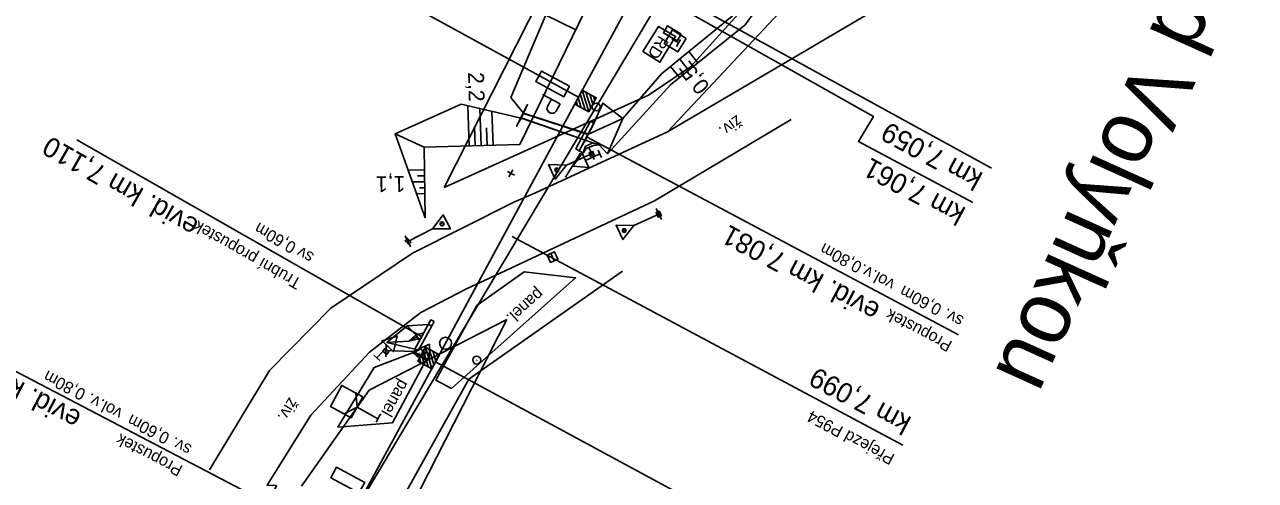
# Model space of a CAD drawing. Extents: x -795094 to -794639, y -1135368 to -1134681.
# Drawn here: x -794952.7 to -794797.7, y -1135065.2 to -1135007.8 of the extents above; entities that cross this region are included whole.
import ezdxf

# ---------------------------------------------------------------- set-up
doc = ezdxf.new("R2010")
doc.units = 0
for name, color, linetype in [('0381KM005-009P - Vrstva 1', 7, 'Continuous'), ('0381KM005-009P - Vrstva 12', 7, 'Continuous'), ('0381KM005-009P - Vrstva 13', 7, 'Continuous'), ('0381KM005-009P - Vrstva 16', 7, 'Continuous'), ('0381KM005-009P - Vrstva 17', 7, 'Continuous'), ('0381KM005-009P - Vrstva 19', 7, 'Continuous'), ('0381KM005-009P - Vrstva 2', 7, 'Continuous'), ('0381KM005-009P - Vrstva 23', 7, 'Continuous'), ('0381KM005-009P - Vrstva 25', 7, 'Continuous'), ('0381KM005-009P - Vrstva 28', 7, 'Continuous'), ('0381KM005-009P - Vrstva 3', 7, 'Continuous'), ('0381KM005-009P - Vrstva 33', 7, 'Continuous'), ('0381KM005-009P - Vrstva 4', 7, 'Continuous'), ('0381KM005-009P - Vrstva 43', 7, 'Continuous'), ('0381KM005-009P - Vrstva 48', 7, 'Continuous'), ('0381KM005-009P - Vrstva 49', 7, 'Continuous'), ('0381KM005-009P - Vrstva 51', 7, 'Continuous'), ('0381KM005-009P - Vrstva 7', 7, 'Continuous'), ('hran DP - hran DP', 7, 'Continuous'), ('vyt_sit - polygon', 7, 'Continuous')]:
    doc.layers.add(name, color=color, linetype=linetype)

msp = doc.modelspace()

# ---------------------------------------------------------------- linework, layer by layer
at = {"layer": '0381KM005-009P - Vrstva 1'}
for points in [[(-794874.77, -1135001.82), (-794875.27, -1135002.76), (-794882.94, -1135016.95), (-794888.88, -1135027.93)], [(-794888.88, -1135027.93), (-794896.92, -1135042.83), (-794900.95, -1135050.28), (-794913.19, -1135072.81), (-794931.08, -1135105.64), (-794935.69, -1135114.26)]]:
    msp.add_lwpolyline(points, dxfattribs=at)
at = {"layer": '0381KM005-009P - Vrstva 12'}
for p, q in [((-794881.46, -1135024.4), (-794881.59, -1135023.95)), ((-794881.14, -1135023.79), (-794881.13, -1135023.79)), ((-794872.92, -1135032.06), (-794872.91, -1135032.06)), ((-794872.5, -1135031.85), (-794872.5, -1135031.85)), ((-794907.35, -1135048.62), (-794907.35, -1135048.62)), ((-794907.6, -1135048.97), (-794907.58, -1135048.95)), ((-794907.09, -1135049.34), (-794907.1, -1135049.36)), ((-794906.84, -1135049.01), (-794906.84, -1135049.01))]:
    msp.add_line(p, q, dxfattribs=at)
for points in [[(-794881.59, -1135023.95), (-794881.14, -1135023.79), (-794880.98, -1135024.24), (-794881.46, -1135024.39), (-794881.59, -1135023.95), (-794881.59, -1135023.95), (-794881.13, -1135023.79), (-794880.98, -1135024.24), (-794880.98, -1135024.24)], [(-794880.98, -1135024.24), (-794881.46, -1135024.4), (-794881.46, -1135024.39)], [(-794873.17, -1135031.49), (-794872.8, -1135031.31), (-794872.5, -1135031.85), (-794872.92, -1135032.06), (-794873.17, -1135031.49), (-794873.17, -1135031.5), (-794872.8, -1135031.31), (-794872.5, -1135031.85), (-794872.91, -1135032.06), (-794873.17, -1135031.5)], [(-794904.34, -1135035.49), (-794904.78, -1135035.05), (-794904.46, -1135034.75), (-794904.04, -1135035.23), (-794904.34, -1135035.49)], [(-794907.6, -1135048.97), (-794907.35, -1135048.62), (-794906.84, -1135049.01), (-794907.09, -1135049.34), (-794907.6, -1135048.97)], [(-794907.58, -1135048.95), (-794907.35, -1135048.62), (-794906.84, -1135049.01), (-794907.1, -1135049.36), (-794907.58, -1135048.95)]]:
    msp.add_lwpolyline(points, dxfattribs=at)
at = {"layer": '0381KM005-009P - Vrstva 13'}
msp.add_line((-794884.56, -1135027.04), (-794882.71, -1135024.01), dxfattribs=at)
for points in [[(-794882.37, -1135024.01), (-794882.1, -1135023.18), (-794881.15, -1135022.72), (-794880.34, -1135022.96)], [(-794882.37, -1135024.01), (-794881.98, -1135023.4), (-794881.04, -1135023.04), (-794880.34, -1135022.96)]]:
    msp.add_lwpolyline(points, dxfattribs=at)
at = {"layer": '0381KM005-009P - Vrstva 16'}
for points in [[(-794898.94, -1135053.67), (-794900.91, -1135052.62), (-794895.75, -1135043.22), (-794889.78, -1135038.98), (-794883.31, -1135039.73)], [(-794906.39, -1135057.97), (-794902.12, -1135050.06), (-794903.85, -1135049.17), (-794908.68, -1135051.01), (-794913.25, -1135058.52)]]:
    msp.add_lwpolyline(points, close=True, dxfattribs=at)
at = {"layer": '0381KM005-009P - Vrstva 17'}
msp.add_lwpolyline([(-794906.48, -1135078.85), (-794910.34, -1135076.94), (-794896.76, -1135052.47), (-794877.42, -1135038.88)], dxfattribs=at)
at = {"layer": '0381KM005-009P - Vrstva 19'}
for p, q in [((-794889.88, -1135018.97), (-794881.68, -1135021.6)), ((-794881.72, -1135021.67), (-794889.88, -1135018.99)), ((-794882.1, -1135022.38), (-794890.17, -1135019.59)), ((-794890.16, -1135019.57), (-794882.1, -1135022.38)), ((-794880.99, -1135020.22), (-794880.96, -1135020.15)), ((-794902.71, -1135047.12), (-794946.12, -1135022.34)), ((-794881.93, -1135021.97), (-794835.06, -1135046.89)), ((-794901.41, -1135045.78), (-794901.14, -1135045.23)), ((-794903.29, -1135047.16), (-794904.32, -1135047.68)), ((-794916, -1135071.26), (-794961.47, -1135047.52))]:
    msp.add_line(p, q, dxfattribs=at)
for points in [[(-794890.17, -1135019.59), (-794890.74, -1135020.61), (-794889.35, -1135017.89), (-794889.88, -1135018.97)], [(-794890.17, -1135019.59), (-794890.16, -1135019.57), (-794889.88, -1135018.99), (-794889.88, -1135018.97)], [(-794881.43, -1135019.98), (-794880.96, -1135020.15), (-794881.68, -1135021.6), (-794881.72, -1135021.67), (-794882.1, -1135022.38), (-794882.1, -1135022.38), (-794882.86, -1135023.7)], [(-794903.57, -1135048.72), (-794902.85, -1135047.4), (-794902.85, -1135047.4), (-794902.44, -1135046.65), (-794902.44, -1135046.66), (-794901.89, -1135045.6)], [(-794901.14, -1135045.23), (-794901.54, -1135045.02), (-794901.89, -1135045.6)], [(-794903.11, -1135047.41), (-794904.32, -1135047.68), (-794903.41, -1135046.89)]]:
    msp.add_lwpolyline(points, dxfattribs=at)
for points in [[(-794881.43, -1135019.98), (-794880.99, -1135020.22), (-794882.86, -1135023.7), (-794883.29, -1135023.48)], [(-794903.13, -1135048.93), (-794903.57, -1135048.72), (-794901.89, -1135045.6), (-794901.41, -1135045.78)]]:
    msp.add_lwpolyline(points, close=True, dxfattribs=at)
msp.add_ellipse((-794903.26, -1135047.17), major_axis=(0.173, -0.304), ratio=0.062911, start_param=2.649673, end_param=6.913725, dxfattribs=at)
at = {"layer": '0381KM005-009P - Vrstva 2'}
msp.add_line((-794830.92, -1135025.88), (-794874.77, -1135001.82), dxfattribs=at)
at = {"layer": '0381KM005-009P - Vrstva 23'}
msp.add_lwpolyline([(-794874.82, -1135011.19), (-794872.86, -1135008.04), (-794870.71, -1135009.3), (-794872.68, -1135012.53)], close=True, dxfattribs=at)
at = {"layer": '0381KM005-009P - Vrstva 25'}
msp.add_lwpolyline([(-794870.01, -1135009), (-794870.52, -1135009.86), (-794872.24, -1135008.85), (-794871.74, -1135007.98), (-794870.01, -1135009)], dxfattribs=at)
at = {"layer": '0381KM005-009P - Vrstva 28'}
for p, q in [((-794880.68, -1135018.15), (-794880.73, -1135018.23)), ((-794902.92, -1135049.17), (-794902.97, -1135049.26))]:
    msp.add_line(p, q, dxfattribs=at)
for centre in [(-794880.7, -1135018.19), (-794902.95, -1135049.22)]:
    msp.add_circle(centre, 0.5, dxfattribs=at)
at = {"layer": '0381KM005-009P - Vrstva 3'}
for p, q in [((-794882.94, -1135016.95), (-794926.07, -1134993.29)), ((-794881.65, -1135018.78), (-794882.46, -1135016.07)), ((-794883.05, -1135018.03), (-794883.22, -1135017.47)), ((-794882.59, -1135018.28), (-794882.97, -1135017.01)), ((-794882.12, -1135018.53), (-794882.72, -1135016.54)), ((-794881.4, -1135018.32), (-794882, -1135016.33)), ((-794881.15, -1135017.85), (-794881.53, -1135016.58)), ((-794880.9, -1135017.38), (-794881.06, -1135016.83)), ((-794902.23, -1135048.45), (-794901.42, -1135051.16)), ((-794901.76, -1135048.7), (-794901.17, -1135050.69)), ((-794902.98, -1135049.84), (-794902.82, -1135050.4)), ((-794902.73, -1135049.38), (-794902.35, -1135050.65)), ((-794902.48, -1135048.91), (-794901.89, -1135050.9)), ((-794901.29, -1135048.95), (-794900.92, -1135050.23)), ((-794900.95, -1135050.28), (-794850.2, -1135077.72)), ((-794900.83, -1135049.21), (-794900.66, -1135049.76))]:
    msp.add_line(p, q, dxfattribs=at)
msp.add_lwpolyline([(-794875.27, -1135002.76), (-794845.8, -1135019.38), (-794847.67, -1135022.54), (-794833.28, -1135030.23)], dxfattribs=at)
for points in [[(-794883.41, -1135017.83), (-794882.46, -1135016.07), (-794880.7, -1135017.02), (-794881.65, -1135018.78)], [(-794900.47, -1135049.4), (-794901.42, -1135051.16), (-794903.18, -1135050.2), (-794902.23, -1135048.45)]]:
    msp.add_lwpolyline(points, close=True, dxfattribs=at)
at = {"layer": '0381KM005-009P - Vrstva 33'}
for p, q in [((-794870.35, -1135010.12), (-794871.19, -1135009.59)), ((-794870.08, -1135009.7), (-794870.61, -1135010.55))]:
    msp.add_line(p, q, dxfattribs=at)
for points in [[(-794869.39, -1135009.54), (-794870.45, -1135011.24), (-794872.15, -1135010.18), (-794871.09, -1135008.48), (-794869.39, -1135009.54)], [(-794887.47, -1135016.62), (-794885.26, -1135017.81)], [(-794886.85, -1135018.14), (-794886.35, -1135017.22)], [(-794885.26, -1135017.81), (-794885.76, -1135018.73)], [(-794885.76, -1135018.73), (-794886, -1135018.96), (-794886.46, -1135018.96), (-794886.66, -1135018.86), (-794886.92, -1135018.46), (-794886.85, -1135018.14)]]:
    msp.add_lwpolyline(points, dxfattribs=at)
for points in [[(-794884.07, -1135015.58), (-794884.78, -1135016.89), (-794888.32, -1135014.98), (-794887.61, -1135013.67)], [(-794909.87, -1135065.52), (-794910.59, -1135066.82), (-794914.13, -1135064.9), (-794913.41, -1135063.59)]]:
    msp.add_lwpolyline(points, close=True, dxfattribs=at)
at = {"layer": '0381KM005-009P - Vrstva 4'}
for p, q in [((-794880.96, -1135024.79), (-794881.61, -1135023.37)), ((-794885.44, -1135026.22), (-794885.9, -1135026.04)), ((-794896.92, -1135042.83), (-794888.88, -1135027.93)), ((-794872.48, -1135032.38), (-794873.14, -1135030.97)), ((-794900.36, -1135032.84), (-794899.9, -1135033)), ((-794904.79, -1135034.42), (-794904.09, -1135035.82)), ((-794891.29, -1135034.51), (-794842.11, -1135060.79)), ((-794876.96, -1135033.83), (-794877.42, -1135033.66)), ((-794907.18, -1135048.11), (-794907.23, -1135049.66)), ((-794902.53, -1135048.84), (-794902.2, -1135049.2))]:
    msp.add_line(p, q, dxfattribs=at)
for points in [[(-794881.29, -1135024.08), (-794884.45, -1135025.53), (-794885.86, -1135027.27), (-794886.7, -1135025.45), (-794884.45, -1135025.53)], [(-794872.81, -1135031.68), (-794875.96, -1135033.14), (-794877.36, -1135034.89), (-794878.21, -1135033.08), (-794875.96, -1135033.14)], [(-794904.44, -1135035.12), (-794901.33, -1135033.56), (-794899.98, -1135031.78), (-794899.08, -1135033.56), (-794901.33, -1135033.56)], [(-794907.2, -1135048.89), (-794903.73, -1135049), (-794901.69, -1135048.08), (-794901.75, -1135050.08), (-794903.73, -1135049)]]:
    msp.add_lwpolyline(points, dxfattribs=at)
for centre in [(-794885.67, -1135026.13), (-794900.13, -1135032.92), (-794877.19, -1135033.75), (-794902.37, -1135049.02)]:
    msp.add_circle(centre, 0.248, dxfattribs=at)
at = {"layer": '0381KM005-009P - Vrstva 43'}
msp.add_lwpolyline([(-794886.42, -1135036.65), (-794885.96, -1135036.44), (-794885.54, -1135037.35), (-794886.45, -1135037.77), (-794886.87, -1135036.86), (-794886.42, -1135036.65), (-794885.99, -1135037.56)], dxfattribs=at)
at = {"layer": '0381KM005-009P - Vrstva 48'}
for p, q in [((-794883.29, -1135008.47), (-794887.06, -1135006.62)), ((-794867.9, -1135012.61), (-794869.03, -1135011.2)), ((-794870.23, -1135014.49), (-794871.35, -1135013.1)), ((-794869.07, -1135013.55), (-794870.19, -1135012.15)), ((-794868.48, -1135013.08), (-794869.05, -1135012.38)), ((-794869.65, -1135014.02), (-794870.21, -1135013.32)), ((-794896.71, -1135023.1), (-794896.86, -1135018.05)), ((-794895.21, -1135023.06), (-794895.35, -1135018.4)), ((-794893.71, -1135023.01), (-794893.84, -1135018.74)), ((-794895.96, -1135023.08), (-794896.03, -1135020.65)), ((-794894.46, -1135023.03), (-794894.53, -1135020.8)), ((-794902.33, -1135026.11), (-794904.4, -1135026.14)), ((-794902.32, -1135026.86), (-794903.23, -1135026.88)), ((-794902.31, -1135027.61), (-794903.86, -1135027.63)), ((-794902.3, -1135028.36), (-794902.95, -1135028.37)), ((-794902.29, -1135029.11), (-794903.33, -1135029.13))]:
    msp.add_line(p, q, dxfattribs=at)
at = {"layer": '0381KM005-009P - Vrstva 49'}
for p, q in [((-794883.51, -1134998.27), (-794891.47, -1135016.98)), ((-794879, -1134999.7), (-794890.34, -1135022.91)), ((-794858.24, -1135002.66), (-794861.94, -1135007.83)), ((-794863.12, -1135006.37), (-794872.47, -1135014.02)), ((-794861.94, -1135007.83), (-794871.36, -1135015.4)), ((-794872.47, -1135014.02), (-794877.35, -1135019.62)), ((-794871.36, -1135015.4), (-794879.31, -1135024.09)), ((-794889.88, -1135018.97), (-794891.47, -1135016.98)), ((-794890.74, -1135020.61), (-794890.17, -1135019.59)), ((-794877.35, -1135019.62), (-794881.68, -1135021.6)), ((-794881.68, -1135021.6), (-794880.96, -1135020.15)), ((-794879.31, -1135024.09), (-794877.35, -1135019.62)), ((-794902.37, -1135023.27), (-794906.04, -1135021.56)), ((-794882.86, -1135023.7), (-794882.1, -1135022.38)), ((-794882.1, -1135022.38), (-794881.15, -1135022.72)), ((-794882.86, -1135023.7), (-794882.37, -1135024.01)), ((-794901.89, -1135045.6), (-794902.44, -1135046.66)), ((-794904.51, -1135045.76), (-794903.41, -1135046.89)), ((-794904.32, -1135047.68), (-794903.41, -1135046.89)), ((-794903.57, -1135048.72), (-794902.85, -1135047.4))]:
    msp.add_line(p, q, dxfattribs=at)
for points in [[(-794877.35, -1135019.62), (-794879.88, -1135017.7), (-794880.96, -1135020.15)], [(-794902.25, -1135032.15), (-794906.04, -1135021.56), (-794897.72, -1135017.85), (-794890.17, -1135019.59)], [(-794889.88, -1135018.97), (-794889.35, -1135017.89), (-794890.74, -1135020.61)], [(-794890.34, -1135022.91), (-794902.37, -1135023.27), (-794902.25, -1135032.15)], [(-794882.37, -1135024.01), (-794882.1, -1135023.18), (-794881.15, -1135022.72), (-794880.34, -1135022.96), (-794879.31, -1135024.09)], [(-794901.89, -1135045.6), (-794904.51, -1135045.76), (-794907.1, -1135047.88), (-794903.57, -1135048.72)], [(-794902.44, -1135046.66), (-794903.41, -1135046.89), (-794903.11, -1135047.41), (-794902.85, -1135047.4)], [(-794903.11, -1135047.41), (-794904.32, -1135047.68), (-794907.1, -1135047.88)]]:
    msp.add_lwpolyline(points, dxfattribs=at)
at = {"layer": '0381KM005-009P - Vrstva 51'}
for p, q in [((-794855.73, -1135004.24), (-794871.74, -1135021.34)), ((-794873.35, -1135030.02), (-794856.16, -1135019.75)), ((-794880.04, -1135024.54), (-794880.46, -1135023.63)), ((-794891.1, -1135030.2), (-794888.36, -1135029)), ((-794897.04, -1135041.09), (-794894.17, -1135039.74)), ((-794908.7, -1135049.45), (-794907.97, -1135050.14))]:
    msp.add_line(p, q, dxfattribs=at)
for points in [[(-794871.74, -1135021.34), (-794845.86, -1135006.13), (-794837.37, -1134998.39), (-794824.29, -1134983.58), (-794790.5, -1134931.65), (-794766.19, -1134894.56)], [(-794888.36, -1135029), (-794871.74, -1135021.34)], [(-794880.25, -1135024.08), (-794882.06, -1135024.92), (-794882.48, -1135024.01), (-794883.65, -1135025.65), (-794881.65, -1135025.83), (-794882.06, -1135024.92)], [(-794891.1, -1135030.2), (-794903.86, -1135036.61), (-794914.15, -1135043.55), (-794921.87, -1135051.41), (-794929.42, -1135063.92)], [(-794873.35, -1135030.02), (-794894.17, -1135039.74)], [(-794944.39, -1135111.84), (-794941.44, -1135105.51), (-794923.05, -1135070.46), (-794920.98, -1135065.89), (-794920.98, -1135065.89), (-794922.17, -1135065.85), (-794916.65, -1135057), (-794909.25, -1135049.07), (-794902.79, -1135044.1), (-794897.04, -1135041.09)], [(-794908.33, -1135049.8), (-794906.97, -1135048.33), (-794906.24, -1135049.02), (-794905.78, -1135047.05), (-794907.7, -1135047.65), (-794906.97, -1135048.33)]]:
    msp.add_lwpolyline(points, dxfattribs=at)
at = {"layer": '0381KM005-009P - Vrstva 7'}
for p, q in [((-794891.9, -1135026.31), (-794891.02, -1135026.78)), ((-794891.7, -1135026.99), (-794891.22, -1135026.11)), ((-794895.73, -1135050.04), (-794895.78, -1135050.13)), ((-794910.84, -1135056.03), (-794908.2, -1135057.46)), ((-794908.44, -1135057.9), (-794907.97, -1135057.02))]:
    msp.add_line(p, q, dxfattribs=at)
for points in [[(-794910.84, -1135056.03), (-794910.12, -1135054.71), (-794912.76, -1135053.28), (-794914.19, -1135055.91), (-794911.56, -1135057.34), (-794910.84, -1135056.03)], [(-794912.44, -1135056.87), (-794910.84, -1135056.03), (-794911, -1135054.23)]]:
    msp.add_lwpolyline(points, dxfattribs=at)
for centre, radius in [((-794899.69, -1135047.96), 0.75), ((-794895.76, -1135050.08), 0.5)]:
    msp.add_circle(centre, radius, dxfattribs=at)
at = {"layer": 'hran DP - hran DP'}
for p, q in [((-794899.86, -1135028.32), (-794880.53, -1134990.11)), ((-794854.54, -1134997.31), (-794868.85, -1135013.13)), ((-794868.85, -1135013.13), (-794874.12, -1135016.68)), ((-794874.12, -1135016.68), (-794899.86, -1135028.32)), ((-794909.29, -1135053.85), (-794891.95, -1135044.96)), ((-794891.95, -1135044.96), (-794908.62, -1135077.55)), ((-794917.84, -1135065.96), (-794909.29, -1135053.85))]:
    msp.add_line(p, q, dxfattribs=at)
at = {"layer": 'vyt_sit - polygon'}
msp.add_line((-794937.71, -1135113.7), (-794869.14, -1134998.77), dxfattribs=at)

# ---------------------------------------------------------------- texts
at = {"layer": '0381KM005-009P - Vrstva 16'}
for rotation, p in [(221.741, (-794888.11, -1135040.9)), (240.3758, (-794905.43, -1135052.38))]:
    msp.add_text('panel.', height=1.5, rotation=rotation, dxfattribs=at).set_placement(p)
at = {"layer": '0381KM005-009P - Vrstva 19'}
for s, height, rotation, p in [('evid. km 7,110', 2.5, 150.2746, (-794930.6, -1135032.56)), ('Trubní propustek', 1.5, 150.2746, (-794917.7, -1135039.96)), ('sv 0,60m', 1.5, 150.2746, (-794916.14, -1135036.71)), ('evid. km 7,081', 2.5, 152.0063, (-794844.78, -1135043.17)), ('sv. 0,60m  vol.v.0,80m', 1.5, 152.0063, (-794834.29, -1135044.69)), ('Propustek', 1.5, 152.0063, (-794835.75, -1135047.8)), ('evid. km 7,140', 2.5, 152.4236, (-794945.4, -1135056.76)), ('sv. 0,60m  vol.v. 0,80m', 1.5, 152.4236, (-794931.54, -1135060.88)), ('Propustek', 1.5, 152.4236, (-794932.67, -1135063.48))]:
    msp.add_text(s, height=height, rotation=rotation, dxfattribs=at).set_placement(p)
at = {"layer": '0381KM005-009P - Vrstva 2'}
msp.add_text('km 7,059', height=2.5, rotation=151.2416, dxfattribs=at).set_placement((-794831.83, -1135026.6))
at = {"layer": '0381KM005-009P - Vrstva 23'}
for s, height, rotation, p in [('žst. Strunkovice nad Volyňkou', 8, 245.663, (-794771.54, -1134921.22)), ('RD', 1.5, 238.5762, (-794872.79, -1135009.08))]:
    msp.add_text(s, height=height, rotation=rotation, dxfattribs=at).set_placement(p)
at = {"layer": '0381KM005-009P - Vrstva 3'}
msp.add_text('km 7,061', height=2.5, rotation=151.8622, dxfattribs=at).set_placement((-794834.01, -1135030.99))
at = {"layer": '0381KM005-009P - Vrstva 4'}
for s, height, p in [('km 7,099', 2.5, (-794840.84, -1135057.37)), ('Přejezd P954', 1.5, (-794842.99, -1135062.04))]:
    msp.add_text(s, height=height, rotation=151.8782, dxfattribs=at).set_placement(p)
at = {"layer": '0381KM005-009P - Vrstva 48'}
for s, rotation, p in [('0,5', 128.7976, (-794866.31, -1135015.57)), ('2,2', 271.7048, (-794896.86, -1135013.83)), ('1,1', 180.7873, (-794904.76, -1135026.88))]:
    msp.add_text(s, height=2, rotation=rotation, dxfattribs=at).set_placement(p)
at = {"layer": '0381KM005-009P - Vrstva 51'}
for rotation, p in [(215.8489, (-794862.99, -1135019.13)), (238.8782, (-794919.38, -1135054.69))]:
    msp.add_text('živ.', height=1.5, rotation=rotation, dxfattribs=at).set_placement(p)

doc.saveas('drawing.dxf')
